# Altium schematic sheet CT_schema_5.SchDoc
size 370 x 333 mm
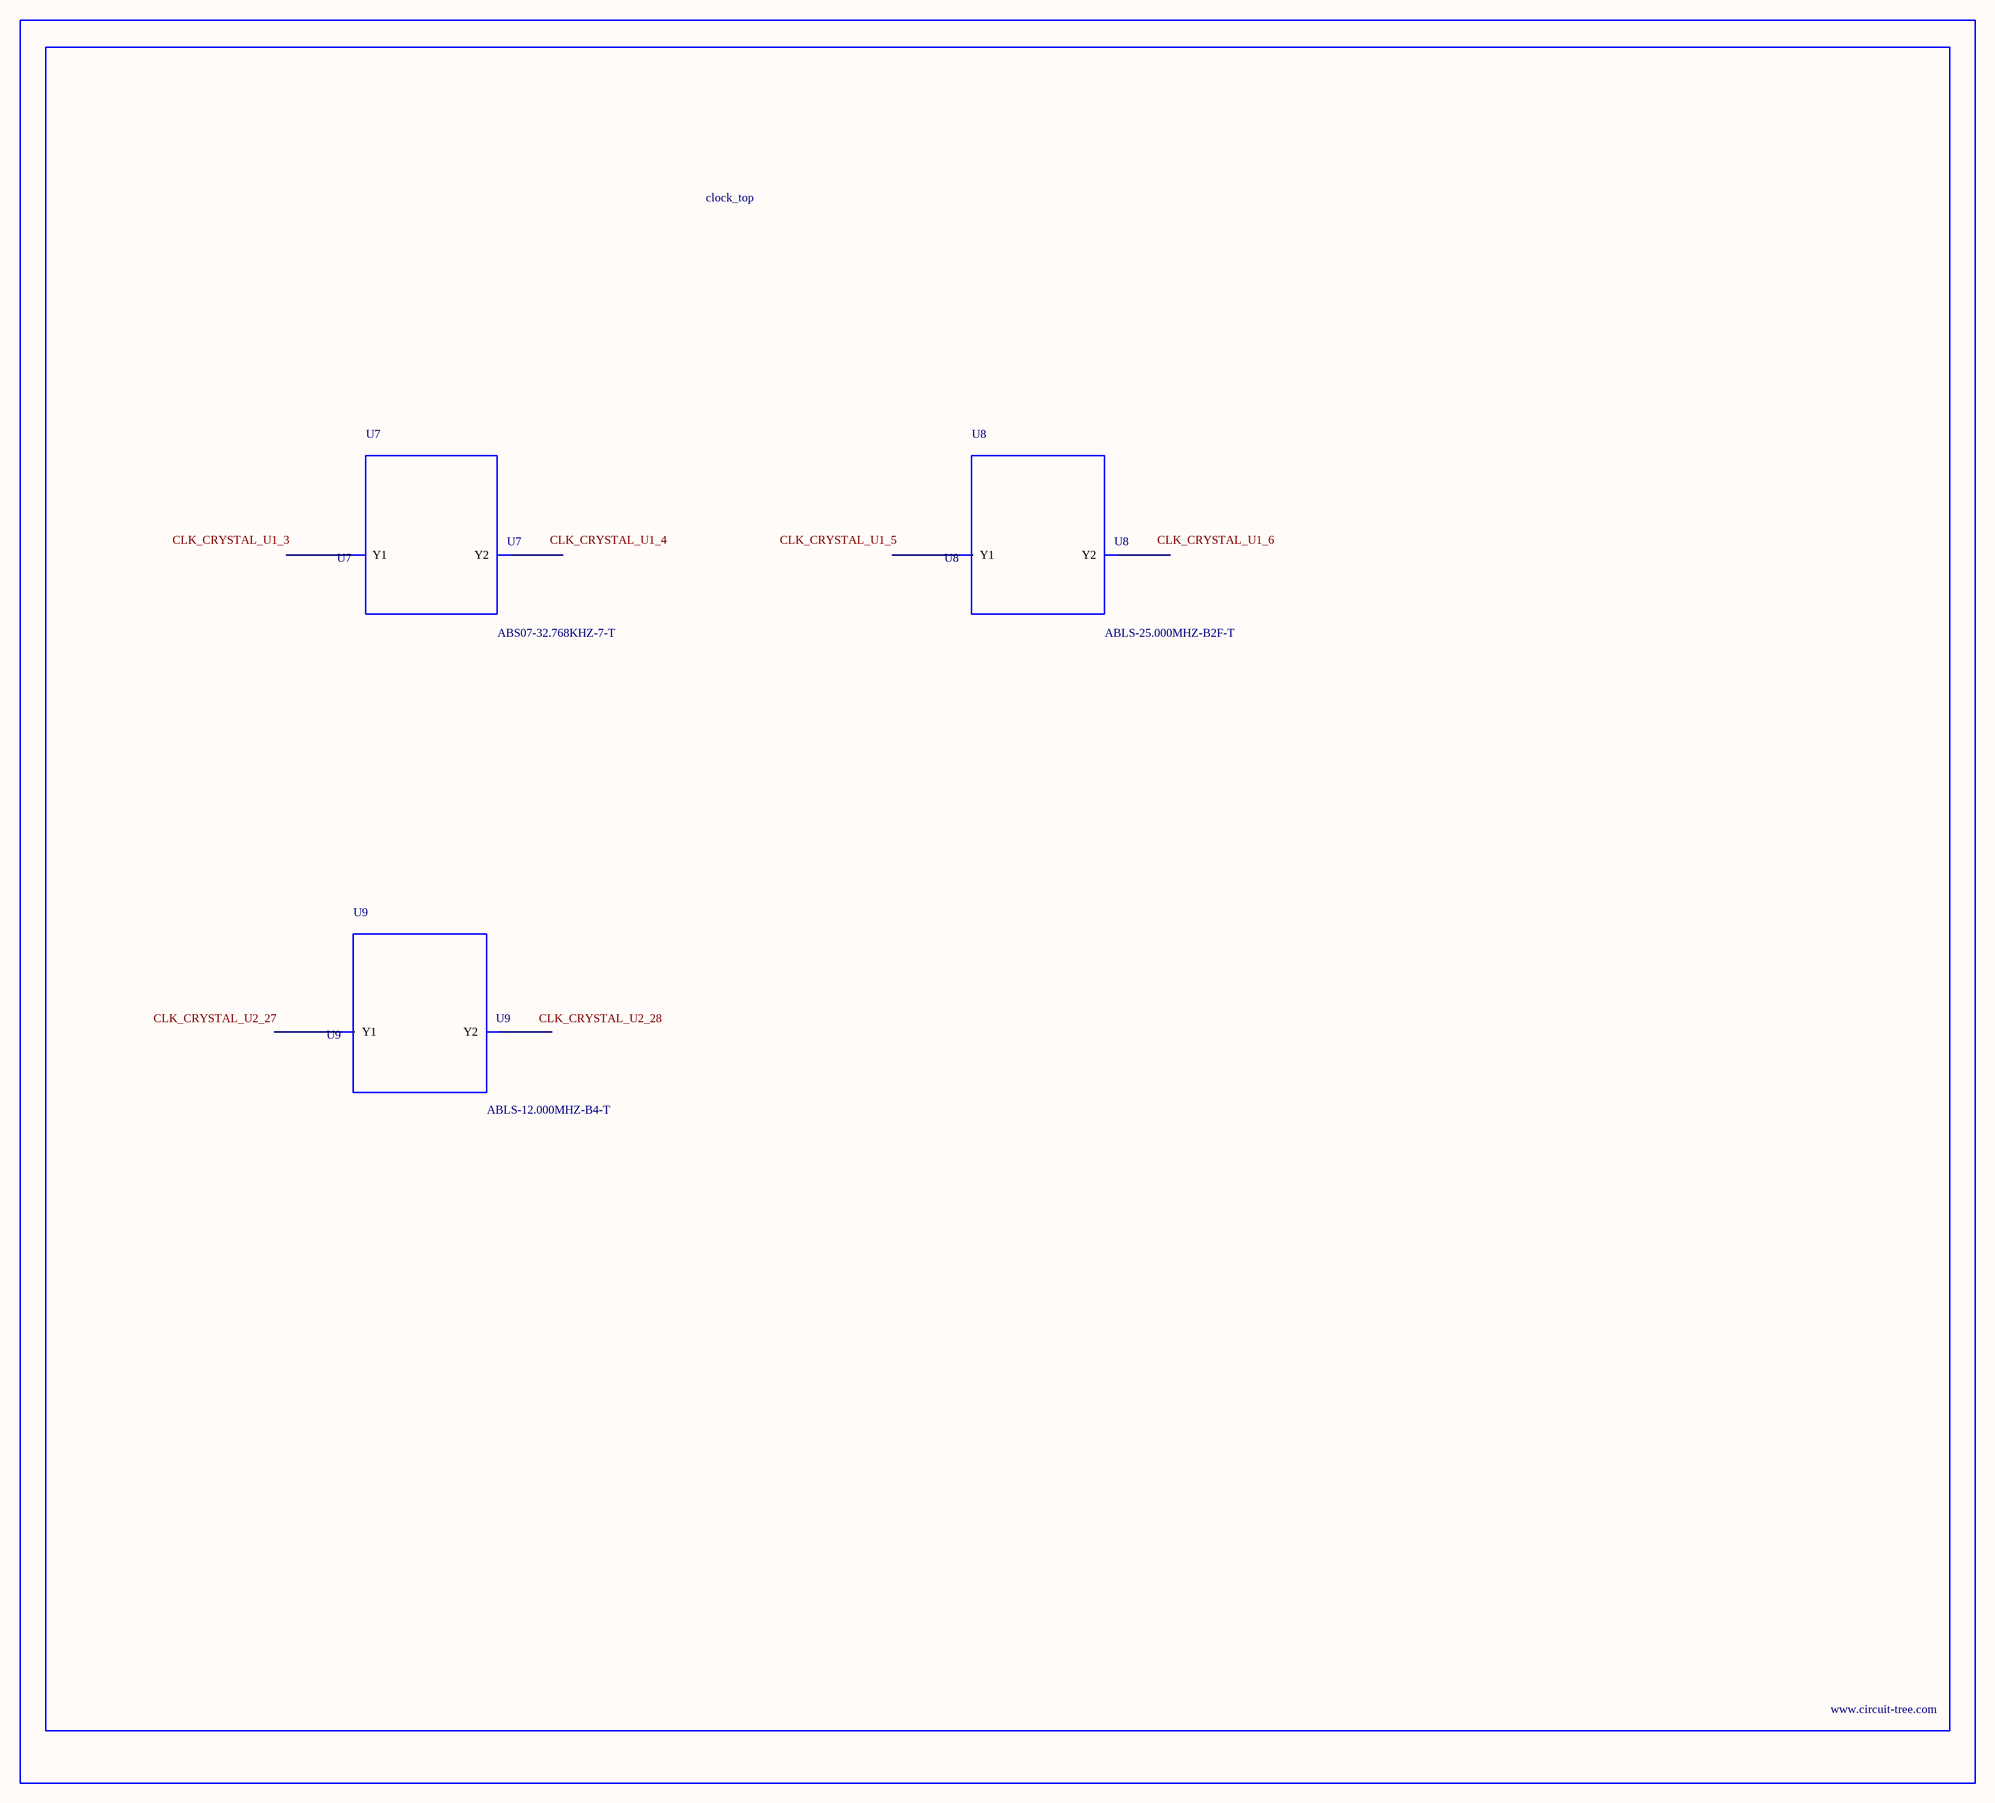
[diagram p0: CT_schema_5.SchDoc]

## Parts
BORDER4  (no value)
U7  ABS07-32.768KHZ-7-T  [ABS07-32.768KHZ-7-T]
U8  ABLS-25.000MHZ-B2F-T  [ABLS-25.000MHZ-B2F-T]
U9  ABLS-12.000MHZ-B4-T  [ABLS-12.000MHZ-B4-T]

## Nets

Not connected (* = marked no-connect by the designer): U7 1(Y1) 2(Y2); U8 1(Y1) 2(Y2); U9 1(Y1) 2(Y2)

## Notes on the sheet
- Labels drawn without touching a wire or pin: CLK_CRYSTAL_U1_3, CLK_CRYSTAL_U1_4, CLK_CRYSTAL_U1_5, CLK_CRYSTAL_U1_6, CLK_CRYSTAL_U2_27, CLK_CRYSTAL_U2_28

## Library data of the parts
BORDER4 = BORDER_PAGE4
